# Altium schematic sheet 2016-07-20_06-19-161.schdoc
size 181 x 111 mm; SheetNumber: 1; SheetTotal: 1
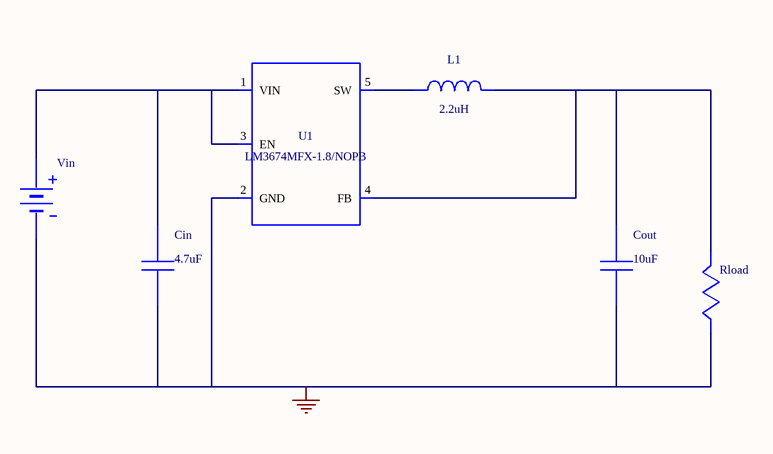
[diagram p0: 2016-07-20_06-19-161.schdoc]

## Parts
Cin  value 4.7uF  (hidden comment: GRM188R60J475KE19D)
Cout  value 10uF  (hidden comment: GRM188R60J106ME47D)
L1  value 2.2uH  (hidden comment: NLCV32T-2R2M-PFR)
Rload  WB_LOAD_RESISTOR  (value not drawn)
U1  LM3674MFX-1.8/NOPB
Vin  WB_BATTERY  (value not drawn)

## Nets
0: Cin.2 Cout.2 Rload.2 U1.2(GND) Vin.2(-)
NetCin_1: Cin.1 U1.1(VIN) U1.3(EN) Vin.1(+)
NetCout_1: Cout.1 L1.2 Rload.1 U1.4(FB)
NetL1_1: L1.1 U1.5(SW)

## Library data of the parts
Cin = GRM188R60J475KE19D: GRM188R60J475KE1; Manufacturer Name: MuRata
Cout = GRM188R60J106ME47D: GRM188R60J106ME4; Manufacturer Name: MuRata
L1 = NLCV32T-2R2M-PFR: Manufacturer Name: TDK
U1 = LM3674MFX-1.8/NOPB: LM3674MFX-1.8/NO; Manufacturer Name: Texas Instruments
